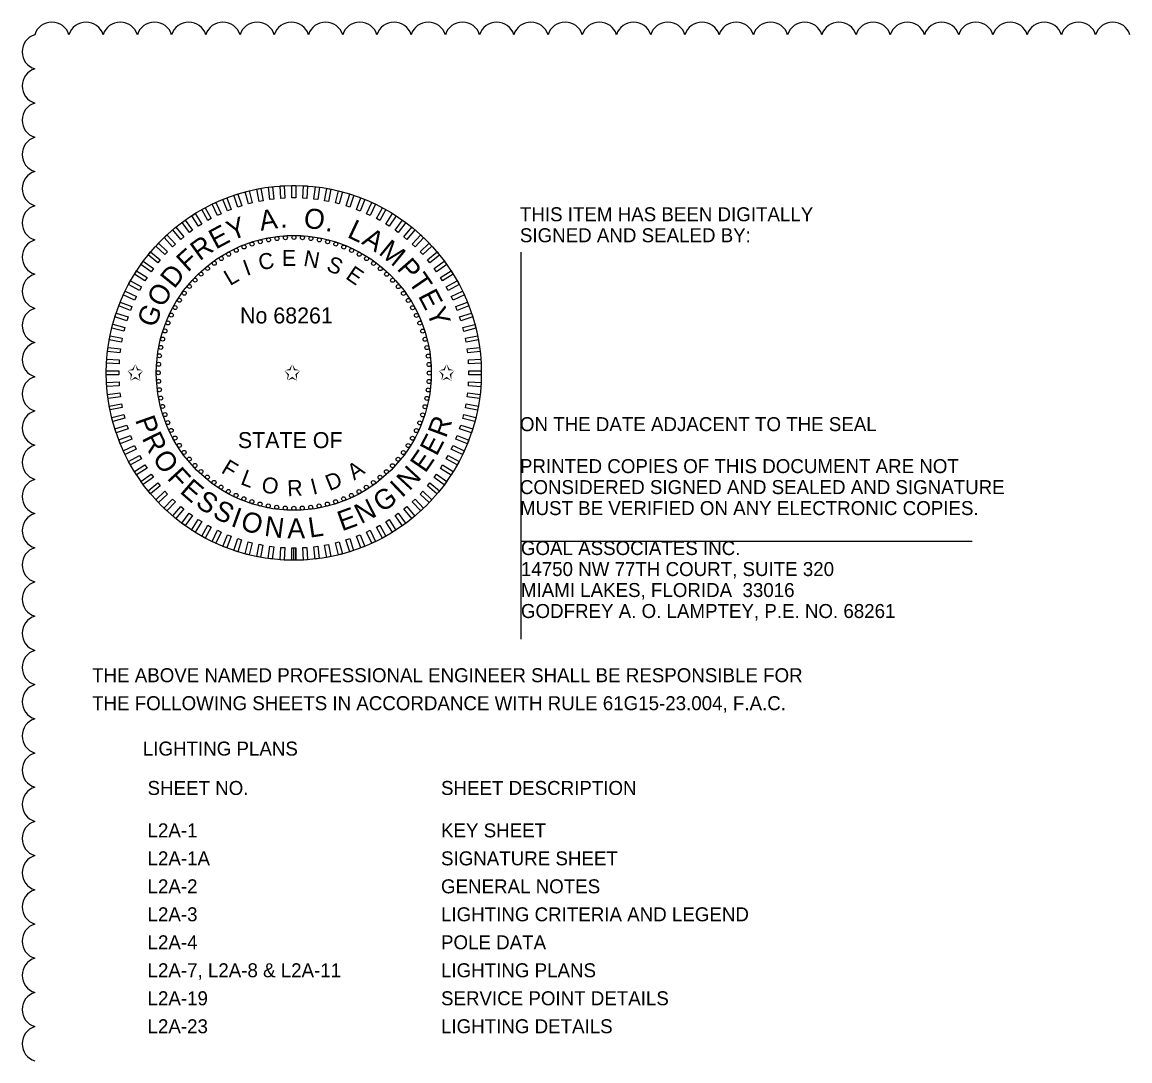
# Model space of a CAD drawing. Extents: x -811 to -790, y -2284 to -2178.
# Drawn here: x -810.85 to -805.31, y -2194.13 to -2188.94 of the extents above; entities that cross this region are included whole.
import ezdxf

# ---------------------------------------------------------------- set-up
doc = ezdxf.new("R2010")
doc.units = 0
for name, color, linetype in [('AdhocPoint_dp', 7, 'Continuous'), ('PlotBorder_dp', 7, 'Continuous'), ('TextMinor', 7, 'Continuous'), ('TextMisc', 7, 'Continuous'), ('TextShtNo', 7, 'Continuous'), ('TextTitle', 7, 'Continuous')]:
    doc.layers.add(name, color=color, linetype=linetype)

msp = doc.modelspace()

# ---------------------------------------------------------------- linework, layer by layer
at = {"layer": 'AdhocPoint_dp'}
for p, q in [((-808.3546, -2190.0892), (-808.3546, -2192.0239)), ((-808.3546, -2191.5339), (-806.0979, -2191.5339))]:
    msp.add_line(p, q, dxfattribs=at)
at = {"layer": 'TextMinor'}
for radius in [0.9375, 0.6875]:
    msp.add_circle((-809.4901, -2190.6926), radius, dxfattribs=at)
at = {"layer": 'TextShtNo'}
for p, q in [((-809.5001, -2191.6301), (-809.5003, -2191.5676)), ((-809.4901, -2191.6301), (-809.4903, -2191.5676)), ((-809.4801, -2191.6301), (-809.4803, -2191.5676))]:
    msp.add_line(p, q, dxfattribs=at)
for points in [[(-809.5897, -2189.8232), (-809.6097, -2189.8257), (-809.6175, -2189.7638), (-809.5975, -2189.7612)], [(-809.5349, -2189.8187), (-809.555, -2189.8199), (-809.559, -2189.7576), (-809.5388, -2189.7563)], [(-809.4799, -2189.8176), (-809.5001, -2189.8176), (-809.5001, -2189.7551), (-809.4799, -2189.7551)], [(-809.425, -2189.8199), (-809.4452, -2189.8187), (-809.4412, -2189.7563), (-809.4211, -2189.7576)], [(-809.3703, -2189.8257), (-809.3904, -2189.8232), (-809.3825, -2189.7613), (-809.3625, -2189.7638)], [(-809.8028, -2189.8753), (-809.8215, -2189.8827), (-809.8445, -2189.8246), (-809.8258, -2189.8172)], [(-809.7508, -2189.8572), (-809.77, -2189.8635), (-809.7893, -2189.8041), (-809.7701, -2189.7979)], [(-809.6979, -2189.8425), (-809.7174, -2189.8475), (-809.7329, -2189.7871), (-809.7134, -2189.782)], [(-809.6441, -2189.8312), (-809.6639, -2189.8349), (-809.6756, -2189.7736), (-809.6558, -2189.7698)], [(-809.3162, -2189.835), (-809.336, -2189.8312), (-809.3243, -2189.7699), (-809.3045, -2189.7736)], [(-809.2626, -2189.8476), (-809.2822, -2189.8426), (-809.2667, -2189.7821), (-809.2471, -2189.7871)], [(-809.21, -2189.8635), (-809.2292, -2189.8573), (-809.2099, -2189.7979), (-809.1907, -2189.8042)], [(-809.1585, -2189.8828), (-809.1773, -2189.8753), (-809.1543, -2189.8173), (-809.1355, -2189.8247)], [(-809.9027, -2189.9209), (-809.9204, -2189.9306), (-809.9505, -2189.8759), (-809.9328, -2189.8662)], [(-809.8535, -2189.8965), (-809.8717, -2189.9051), (-809.8983, -2189.8486), (-809.8801, -2189.84)], [(-809.1083, -2189.9052), (-809.1266, -2189.8966), (-809.1, -2189.8401), (-809.0817, -2189.8487)], [(-809.0596, -2189.9307), (-809.0773, -2189.921), (-809.0473, -2189.8663), (-809.0296, -2189.876)], [(-809.9962, -2189.9787), (-810.0125, -2189.9906), (-810.0492, -2189.94), (-810.0329, -2189.9282)], [(-809.9504, -2189.9483), (-809.9674, -2189.9591), (-810.0009, -2189.9064), (-809.9838, -2189.8956)], [(-809.0127, -2189.9592), (-809.0297, -2189.9484), (-808.9962, -2189.8957), (-808.9792, -2189.9065)], [(-808.9676, -2189.9907), (-808.9839, -2189.9788), (-808.9472, -2189.9283), (-808.9308, -2189.9402)], [(-810.04, -2190.0119), (-810.0556, -2190.0247), (-810.0954, -2189.9766), (-810.0798, -2189.9638)], [(-808.9245, -2190.0249), (-808.9401, -2190.012), (-808.9003, -2189.9639), (-808.8847, -2189.9768)], [(-810.0817, -2190.0478), (-810.0964, -2190.0616), (-810.1392, -2190.0161), (-810.1244, -2190.0022)], [(-808.8837, -2190.0617), (-808.8984, -2190.0479), (-808.8557, -2190.0024), (-808.841, -2190.0162)], [(-810.1579, -2190.127), (-810.1707, -2190.1425), (-810.2188, -2190.1027), (-810.206, -2190.0872)], [(-810.121, -2190.0862), (-810.1348, -2190.1009), (-810.1804, -2190.0581), (-810.1665, -2190.0434)], [(-808.8453, -2190.101), (-808.8591, -2190.0863), (-808.8136, -2190.0436), (-808.7998, -2190.0583)], [(-808.8094, -2190.1427), (-808.8223, -2190.1271), (-808.7742, -2190.0873), (-808.7613, -2190.1029)], [(-810.192, -2190.17), (-810.2039, -2190.1864), (-810.2544, -2190.1497), (-810.2426, -2190.1333)], [(-808.7762, -2190.1865), (-808.7881, -2190.1702), (-808.7376, -2190.1335), (-808.7257, -2190.1498)], [(-810.2235, -2190.2151), (-810.2343, -2190.2322), (-810.287, -2190.1987), (-810.2762, -2190.1817)], [(-808.7459, -2190.2323), (-808.7567, -2190.2153), (-808.7039, -2190.1818), (-808.6931, -2190.1989)], [(-810.252, -2190.2621), (-810.2617, -2190.2798), (-810.3164, -2190.2497), (-810.3067, -2190.232)], [(-808.7184, -2190.28), (-808.7281, -2190.2623), (-808.6734, -2190.2322), (-808.6637, -2190.2499)], [(-810.2775, -2190.3108), (-810.2861, -2190.3291), (-810.3426, -2190.3025), (-810.334, -2190.2842)], [(-808.694, -2190.3292), (-808.7026, -2190.311), (-808.6461, -2190.2844), (-808.6375, -2190.3027)], [(-810.3, -2190.361), (-810.3074, -2190.3798), (-810.3654, -2190.3568), (-810.358, -2190.338)], [(-808.6728, -2190.3799), (-808.6802, -2190.3612), (-808.6222, -2190.3382), (-808.6147, -2190.357)], [(-810.3192, -2190.4125), (-810.3254, -2190.4317), (-810.3848, -2190.4124), (-810.3786, -2190.3932)], [(-808.6548, -2190.4319), (-808.661, -2190.4127), (-808.6016, -2190.3934), (-808.5954, -2190.4126)], [(-810.3351, -2190.4651), (-810.3401, -2190.4847), (-810.4006, -2190.4691), (-810.3956, -2190.4496)], [(-808.64, -2190.4849), (-808.6451, -2190.4653), (-808.5846, -2190.4498), (-808.5796, -2190.4693)], [(-810.3477, -2190.5186), (-810.3515, -2190.5385), (-810.4129, -2190.5268), (-810.4091, -2190.5069)], [(-808.6287, -2190.5386), (-808.6325, -2190.5188), (-808.5711, -2190.5071), (-808.5673, -2190.5269)], [(-810.357, -2190.5728), (-810.3595, -2190.5928), (-810.4215, -2190.585), (-810.4189, -2190.565)], [(-808.6207, -2190.593), (-808.6232, -2190.573), (-808.5613, -2190.5652), (-808.5588, -2190.5852)], [(-810.3628, -2190.6275), (-810.3641, -2190.6476), (-810.4264, -2190.6437), (-810.4251, -2190.6236)], [(-808.6162, -2190.6478), (-808.6174, -2190.6277), (-808.5551, -2190.6238), (-808.5539, -2190.6439)], [(-810.3652, -2190.6824), (-810.3652, -2190.7026), (-810.4276, -2190.7026), (-810.4276, -2190.6824)], [(-808.6151, -2190.7028), (-808.6151, -2190.6826), (-808.5527, -2190.6826), (-808.5527, -2190.7028)], [(-810.3641, -2190.7374), (-810.3628, -2190.7575), (-810.4251, -2190.7614), (-810.4264, -2190.7413)], [(-808.6175, -2190.7577), (-808.6162, -2190.7376), (-808.5539, -2190.7415), (-808.5551, -2190.7616)], [(-810.3595, -2190.7922), (-810.357, -2190.8122), (-810.4189, -2190.82), (-810.4215, -2190.8)], [(-808.6233, -2190.8124), (-808.6207, -2190.7923), (-808.5588, -2190.8002), (-808.5613, -2190.8202)], [(-810.3516, -2190.8466), (-810.3478, -2190.8664), (-810.4091, -2190.8781), (-810.4129, -2190.8583)], [(-808.6325, -2190.8666), (-808.6287, -2190.8467), (-808.5674, -2190.8584), (-808.5712, -2190.8783)], [(-810.3402, -2190.9003), (-810.3352, -2190.9199), (-810.3957, -2190.9354), (-810.4007, -2190.9159)], [(-808.6451, -2190.9201), (-808.6401, -2190.9005), (-808.5796, -2190.916), (-808.5846, -2190.9356)], [(-810.3255, -2190.9533), (-810.3192, -2190.9725), (-810.3786, -2190.9918), (-810.3849, -2190.9726)], [(-808.6611, -2190.9727), (-808.6548, -2190.9535), (-808.5954, -2190.9728), (-808.6017, -2190.992)], [(-810.3075, -2191.0052), (-810.3, -2191.024), (-810.3581, -2191.047), (-810.3655, -2191.0282)], [(-808.6803, -2191.0242), (-808.6729, -2191.0054), (-808.6148, -2191.0284), (-808.6222, -2191.0472)], [(-810.2862, -2191.0559), (-810.2776, -2191.0742), (-810.3341, -2191.1008), (-810.3427, -2191.0825)], [(-808.7027, -2191.0744), (-808.6941, -2191.0561), (-808.6376, -2191.0827), (-808.6462, -2191.101)], [(-810.2618, -2191.1052), (-810.2521, -2191.1229), (-810.3068, -2191.153), (-810.3165, -2191.1353)], [(-808.7282, -2191.1231), (-808.7185, -2191.1054), (-808.6638, -2191.1355), (-808.6735, -2191.1532)], [(-810.2344, -2191.1529), (-810.2236, -2191.1699), (-810.2763, -2191.2034), (-810.2871, -2191.1863)], [(-810.204, -2191.1987), (-810.1922, -2191.215), (-810.2427, -2191.2517), (-810.2545, -2191.2354)], [(-808.7882, -2191.2152), (-808.7763, -2191.1988), (-808.7258, -2191.2355), (-808.7377, -2191.2519)], [(-808.7568, -2191.1701), (-808.746, -2191.153), (-808.6932, -2191.1865), (-808.704, -2191.2035)], [(-810.1708, -2191.2425), (-810.158, -2191.2581), (-810.2061, -2191.2979), (-810.2189, -2191.2823)], [(-808.8224, -2191.2582), (-808.8095, -2191.2427), (-808.7614, -2191.2825), (-808.7743, -2191.298)], [(-810.135, -2191.2842), (-810.1211, -2191.2989), (-810.1667, -2191.3416), (-810.1805, -2191.3269)], [(-808.8592, -2191.299), (-808.8454, -2191.2843), (-808.7999, -2191.327), (-808.8137, -2191.3418)], [(-810.0965, -2191.3235), (-810.0818, -2191.3373), (-810.1246, -2191.3828), (-810.1393, -2191.369)], [(-810.0557, -2191.3603), (-810.0402, -2191.3732), (-810.08, -2191.4213), (-810.0955, -2191.4084)], [(-808.9402, -2191.3733), (-808.9247, -2191.3604), (-808.8848, -2191.4086), (-808.9004, -2191.4214)], [(-808.8985, -2191.3374), (-808.8838, -2191.3236), (-808.8411, -2191.3691), (-808.8558, -2191.383)], [(-810.0127, -2191.3945), (-809.9964, -2191.4064), (-810.0331, -2191.4569), (-810.0494, -2191.445)], [(-808.984, -2191.4065), (-808.9677, -2191.3946), (-808.931, -2191.4451), (-808.9473, -2191.457)], [(-809.9676, -2191.426), (-809.9505, -2191.4368), (-809.984, -2191.4895), (-810.001, -2191.4787)], [(-809.9206, -2191.4545), (-809.9029, -2191.4642), (-809.933, -2191.5189), (-809.9507, -2191.5092)], [(-809.0775, -2191.4643), (-809.0598, -2191.4546), (-809.0297, -2191.5093), (-809.0474, -2191.519)], [(-809.0299, -2191.4369), (-809.0128, -2191.4261), (-808.9794, -2191.4788), (-808.9964, -2191.4896)], [(-809.8719, -2191.48), (-809.8536, -2191.4886), (-809.8802, -2191.5451), (-809.8985, -2191.5365)], [(-809.8217, -2191.5024), (-809.8029, -2191.5099), (-809.8259, -2191.5679), (-809.8447, -2191.5605)], [(-809.7702, -2191.5217), (-809.751, -2191.5279), (-809.7703, -2191.5873), (-809.7895, -2191.581)], [(-809.2294, -2191.5279), (-809.2102, -2191.5217), (-809.1909, -2191.5811), (-809.2101, -2191.5873)], [(-809.1775, -2191.5099), (-809.1587, -2191.5025), (-809.1357, -2191.5606), (-809.1545, -2191.568)], [(-809.1268, -2191.4887), (-809.1085, -2191.4801), (-809.0819, -2191.5366), (-809.1002, -2191.5452)], [(-809.7176, -2191.5376), (-809.698, -2191.5426), (-809.7136, -2191.6031), (-809.7331, -2191.5981)], [(-809.6641, -2191.5502), (-809.6443, -2191.554), (-809.656, -2191.6153), (-809.6758, -2191.6116)], [(-809.6099, -2191.5594), (-809.5899, -2191.562), (-809.5977, -2191.6239), (-809.6177, -2191.6214)], [(-809.5552, -2191.5653), (-809.5351, -2191.5665), (-809.539, -2191.6288), (-809.5592, -2191.6276)], [(-809.5003, -2191.5676), (-809.4801, -2191.5676), (-809.4801, -2191.6301), (-809.5003, -2191.6301)], [(-809.4453, -2191.5665), (-809.4252, -2191.5653), (-809.4213, -2191.6276), (-809.4414, -2191.6289)], [(-809.3906, -2191.562), (-809.3705, -2191.5595), (-809.3627, -2191.6214), (-809.3827, -2191.624)], [(-809.3362, -2191.554), (-809.3163, -2191.5503), (-809.3046, -2191.6116), (-809.3245, -2191.6154)], [(-809.2824, -2191.5427), (-809.2628, -2191.5376), (-809.2473, -2191.5981), (-809.2668, -2191.6031)]]:
    msp.add_lwpolyline(points, close=True, dxfattribs=at)
for centre in [(-809.6989, -2190.0481), (-809.6581, -2190.0363), (-809.6165, -2190.027), (-809.5745, -2190.0204), (-809.5321, -2190.0164), (-809.4896, -2190.0151), (-809.447, -2190.0165), (-809.4047, -2190.0205), (-809.3626, -2190.0272), (-809.3211, -2190.0366), (-809.2802, -2190.0485), (-809.816, -2190.0987), (-809.7781, -2190.0794), (-809.739, -2190.0625), (-809.2402, -2190.0629), (-809.2012, -2190.0798), (-809.1633, -2190.0992), (-809.8879, -2190.1442), (-809.8527, -2190.1203), (-809.1266, -2190.1209), (-809.0915, -2190.1448), (-809.9535, -2190.1984), (-809.9215, -2190.1702), (-809.0579, -2190.171), (-809.026, -2190.1991), (-810.0118, -2190.2603), (-809.9836, -2190.2284), (-808.9959, -2190.2292), (-808.9678, -2190.2612), (-810.0379, -2190.2939), (-808.9417, -2190.2948), (-810.0835, -2190.3657), (-810.0618, -2190.3291), (-808.9178, -2190.3301), (-808.8962, -2190.3667), (-810.1029, -2190.4036), (-808.8769, -2190.4047), (-810.1343, -2190.4827), (-810.1198, -2190.4427), (-808.86, -2190.4437), (-808.8456, -2190.4838), (-810.1462, -2190.5236), (-808.8338, -2190.5247), (-810.1555, -2190.5651), (-808.8245, -2190.5662), (-810.1662, -2190.6495), (-810.1622, -2190.6071), (-808.8179, -2190.6082), (-808.814, -2190.6506), (-810.1676, -2190.692), (-808.8127, -2190.6932), (-810.1663, -2190.7346), (-808.814, -2190.7357), (-810.1623, -2190.7769), (-810.1557, -2190.819), (-808.8248, -2190.8201), (-808.8181, -2190.7781), (-810.1464, -2190.8605), (-808.8341, -2190.8616), (-810.1346, -2190.9014), (-808.846, -2190.9025), (-810.1202, -2190.9415), (-810.1034, -2190.9805), (-808.8774, -2190.9816), (-808.8604, -2190.9425), (-810.0841, -2191.0185), (-808.8967, -2191.0195), (-810.0624, -2191.0551), (-810.0385, -2191.0903), (-808.9424, -2191.0913), (-808.9184, -2191.0561), (-810.0125, -2191.124), (-809.9844, -2191.1559), (-808.9967, -2191.1568), (-808.9685, -2191.1249), (-809.9543, -2191.1861), (-809.0268, -2191.1868), (-809.9224, -2191.2142), (-809.8888, -2191.2403), (-809.8536, -2191.2643), (-809.1276, -2191.2649), (-809.0924, -2191.241), (-809.0587, -2191.215), (-809.817, -2191.286), (-809.7791, -2191.3053), (-809.74, -2191.3223), (-809.2413, -2191.3227), (-809.2022, -2191.3058), (-809.1642, -2191.2865), (-809.7, -2191.3367), (-809.6591, -2191.3486), (-809.6176, -2191.358), (-809.5756, -2191.3647), (-809.5332, -2191.3687), (-809.4901, -2191.3701), (-809.4481, -2191.3688), (-809.4058, -2191.3648), (-809.3637, -2191.3582), (-809.3222, -2191.3489), (-809.2813, -2191.3371)]:
    msp.add_circle(centre, 0.01, dxfattribs=at)
at = {"layer": 'TextTitle'}
for centre, start, end in [((-810.7002, -2189.0276), 17.5, 162.5), ((-810.5291, -2189.0276), 17.5, 162.5), ((-810.358, -2189.0276), 17.5, 162.5), ((-810.1868, -2189.0276), 17.5, 162.5), ((-810.0157, -2189.0276), 17.5, 162.5), ((-809.8446, -2189.0276), 17.5, 162.5), ((-809.6735, -2189.0276), 17.5, 162.5), ((-809.5024, -2189.0276), 17.5, 162.5), ((-809.3312, -2189.0276), 17.5, 162.5), ((-809.1601, -2189.0276), 17.5, 162.5), ((-808.989, -2189.0276), 17.5, 162.5), ((-808.8179, -2189.0276), 17.5, 162.5), ((-808.6467, -2189.0276), 17.5, 162.5), ((-808.4756, -2189.0276), 17.5, 162.5), ((-808.3045, -2189.0276), 17.5, 162.5), ((-808.1334, -2189.0276), 17.5, 162.5), ((-807.9622, -2189.0276), 17.5, 162.5), ((-807.7911, -2189.0276), 17.5, 162.5), ((-807.62, -2189.0276), 17.5, 162.5), ((-807.4489, -2189.0276), 17.5, 162.5), ((-807.2778, -2189.0276), 17.5, 162.5), ((-807.1066, -2189.0276), 17.5, 162.5), ((-806.9355, -2189.0276), 17.5, 162.5), ((-806.7644, -2189.0276), 17.5, 162.5), ((-806.5933, -2189.0276), 17.5, 162.5), ((-806.4221, -2189.0276), 17.5, 162.5), ((-806.251, -2189.0276), 17.5, 162.5), ((-806.0799, -2189.0276), 17.5, 162.5), ((-805.9088, -2189.0276), 17.5, 162.5), ((-805.7377, -2189.0276), 17.5, 162.5), ((-805.5665, -2189.0276), 17.5, 162.5), ((-805.3954, -2189.0276), 17.5, 162.5), ((-810.7588, -2189.0862), 107.5, 252.5), ((-810.7588, -2189.2573), 107.5, 252.5), ((-810.7588, -2189.4284), 107.5, 252.5), ((-810.7588, -2189.5996), 107.5, 252.5), ((-810.7588, -2189.7707), 107.5, 252.5), ((-810.7588, -2189.9418), 107.5, 252.5), ((-810.7588, -2190.1129), 107.5, 252.5), ((-810.7588, -2190.2841), 107.5, 252.5), ((-810.7588, -2190.4552), 107.5, 252.5), ((-810.7588, -2190.6263), 107.5, 252.5), ((-810.7588, -2190.7974), 107.5, 252.5), ((-810.7588, -2190.9685), 107.5, 252.5), ((-810.7588, -2191.1397), 107.5, 252.5), ((-810.7588, -2191.3108), 107.5, 252.5), ((-810.7588, -2191.4819), 107.5, 252.5), ((-810.7588, -2191.653), 107.5, 252.5), ((-810.7588, -2191.8242), 107.5, 252.5), ((-810.7588, -2191.9953), 107.5, 252.5), ((-810.7588, -2192.1664), 107.5, 252.5), ((-810.7588, -2192.3375), 107.5, 252.5), ((-810.7588, -2192.5087), 107.5, 252.5), ((-810.7588, -2192.6798), 107.5, 252.5), ((-810.7588, -2192.8509), 107.5, 252.5), ((-810.7588, -2193.022), 107.5, 252.5), ((-810.7588, -2193.1931), 107.5, 252.5), ((-810.7588, -2193.3643), 107.5, 252.5), ((-810.7588, -2193.5354), 107.5, 252.5), ((-810.7588, -2193.7065), 107.5, 252.5), ((-810.7588, -2193.8776), 107.5, 252.5), ((-810.7588, -2194.0488), 107.5, 252.5)]:
    msp.add_arc(centre, 0.0897, start, end, dxfattribs=at)

# ---------------------------------------------------------------- texts
at = {"layer": 'PlotBorder_dp'}
for s, p in [('THIS ITEM HAS BEEN DIGITALLY', (-808.3596, -2189.934)), ('SIGNED AND SEALED BY:', (-808.3596, -2190.039)), ('ON THE DATE ADJACENT TO THE SEAL', (-808.3596, -2190.984)), ('PRINTED COPIES OF THIS DOCUMENT ARE NOT ', (-808.3596, -2191.194)), ('CONSIDERED SIGNED AND SEALED AND SIGNATURE ', (-808.3596, -2191.299)), ('MUST BE VERIFIED ON ANY ELECTRONIC COPIES.', (-808.3596, -2191.404)), ('GOAL ASSOCIATES INC.', (-808.3546, -2191.6039)), ('14750 NW 77TH COURT, SUITE 320', (-808.3546, -2191.7089)), ('MIAMI LAKES, FLORIDA  33016', (-808.3546, -2191.8139)), ('GODFREY A. O. LAMPTEY, P.E. NO. 68261', (-808.3546, -2191.9189)), ('THE ABOVE NAMED PROFESSIONAL ENGINEER SHALL BE RESPONSIBLE FOR ', (-810.4987, -2192.24)), ('THE FOLLOWING SHEETS IN ACCORDANCE WITH RULE 61G15-23.004, F.A.C.', (-810.4987, -2192.38)), ('LIGHTING PLANS', (-810.245, -2192.6071))]:
    msp.add_text(s, height=0.07, dxfattribs=at).set_placement(p)
at = {"layer": 'TextMisc'}
for s, p in [('SHEET NO.', (-810.2215, -2192.8041)), ('SHEET DESCRIPTION', (-808.7542, -2192.8041)), ('L2A-1', (-810.2215, -2193.0162)), ('KEY SHEET', (-808.7542, -2193.0162)), ('L2A-1A', (-810.2215, -2193.1562)), ('SIGNATURE SHEET', (-808.7542, -2193.1562)), ('L2A-2', (-810.2215, -2193.2962)), ('GENERAL NOTES', (-808.7542, -2193.2962)), ('L2A-3', (-810.2215, -2193.4362)), ('LIGHTING CRITERIA AND LEGEND', (-808.7542, -2193.4362)), ('L2A-4 ', (-810.2215, -2193.5762)), ('POLE DATA', (-808.7542, -2193.5762)), ('L2A-7, L2A-8 & L2A-11', (-810.2215, -2193.7162)), ('LIGHTING PLANS', (-808.7542, -2193.7162)), ('L2A-19', (-810.2215, -2193.8562)), ('SERVICE POINT DETAILS', (-808.7542, -2193.8562)), ('L2A-23', (-810.2215, -2193.9962)), ('LIGHTING DETAILS', (-808.7542, -2193.9962))]:
    msp.add_text(s, height=0.07, dxfattribs=at).set_placement(p)
at = {"layer": 'TextShtNo'}
for s, height, rotation, p in [('O', 0.1, 352.1877, (-809.4449, -2189.9645)), ('Y', 0.1, 21.0633, (-809.8021, -2190.0332)), ('A', 0.1, 8.8088, (-809.6551, -2189.982)), ('L', 0.1, 334.6727, (-809.2279, -2190.0118)), ('E', 0.1, 28.1055, (-809.8806, -2190.0764)), ('.', 0.1, 1.0418, (-809.5575, -2189.9662)), ('.', 0.1, 343.5268, (-809.3358, -2189.9796)), ('A', 0.1, 328.4096, (-809.1552, -2190.0445)), ('R', 0.1, 35.9269, (-809.9609, -2190.1353)), ('M', 0.1, 320.6426, (-809.0707, -2190.0957)), ('F', 0.1, 42.3772, (-810.0205, -2190.1917)), ('C', 0.08, 12.2025, (-809.6579, -2190.181)), ('E', 0.08, 0.4186, (-809.5498, -2190.1575)), ('N', 0.08, 349.2914, (-809.4455, -2190.1561)), ('I', 0.08, 20.0117, (-809.7258, -2190.2085)), ('S', 0.08, 337.0221, (-809.3325, -2190.1778)), ('P', 0.1, 311.1966, (-808.9784, -2190.1727)), ('D', 0.1, 50.8569, (-810.0886, -2190.2754)), ('L', 0.08, 30.4021, (-809.8093, -2190.259)), ('E', 0.08, 325.8663, (-809.2358, -2190.218)), ('T', 0.1, 304.4563, (-808.9209, -2190.2363)), ('O', 0.1, 59.5178, (-810.1446, -2190.3702)), ('E', 0.1, 297.6315, (-808.8707, -2190.3072)), ('G', 0.1, 68.0518, (-810.1851, -2190.4709)), ('Y', 0.1, 290.5893, (-808.8281, -2190.386)), ('P', 0.1, 289.4055, (-810.2848, -2190.9272)), ('R', 0.1, 69.5134, (-808.7299, -2191.0223)), ('R', 0.1, 296.1458, (-810.2518, -2191.0188)), ('E', 0.1, 62.4712, (-808.7761, -2191.113)), ('O', 0.1, 303.9671, (-810.2003, -2191.1194)), ('E', 0.1, 55.4289, (-808.833, -2191.1974)), ('F', 0.08, 328.7241, (-809.8582, -2191.1892)), ('A', 0.08, 34.4992, (-809.1883, -2191.232)), ('F', 0.1, 312.628, (-810.1279, -2191.2215)), ('L', 0.08, 339.2916, (-809.7609, -2191.2483)), ('D', 0.08, 22.0128, (-809.312, -2191.2845)), ('N', 0.1, 47.1788, (-808.9123, -2191.2864)), ('E', 0.1, 319.0783, (-810.0645, -2191.2898)), ('O', 0.08, 349.6821, (-809.6562, -2191.288)), ('R', 0.08, 2.3398, (-809.5217, -2191.3099)), ('I', 0.08, 14.2037, (-809.3941, -2191.3032)), ('I', 0.1, 43.6456, (-808.9499, -2191.3209)), ('S', 0.1, 326.1206, (-809.9869, -2191.3557)), ('G', 0.1, 35.1115, (-809.0492, -2191.3941)), ('S', 0.1, 333.193, (-809.9015, -2191.4119)), ('I', 0.1, 340.2654, (-809.8098, -2191.457)), ('E', 0.1, 19.8191, (-809.2498, -2191.4856)), ('N', 0.1, 26.8614, (-809.1544, -2191.4501)), ('O', 0.1, 343.7986, (-809.7621, -2191.4753)), ('N', 0.1, 352.4595, (-809.6411, -2191.5073)), ('A', 0.1, 0.7097, (-809.5227, -2191.5206)), ('L', 0.1, 8.4767, (-809.4105, -2191.5174))]:
    msp.add_text(s, height=height, rotation=rotation, dxfattribs=at).set_placement(p)
for s, p in [('No 68261', (-809.7591, -2190.4454)), ('✩', (-810.3251, -2190.7305)), ('✩', (-809.5404, -2190.7305)), ('✩', (-808.7685, -2190.7305)), ('STATE OF', (-809.7698, -2191.0688))]:
    msp.add_text(s, height=0.08, dxfattribs=at).set_placement(p)

doc.saveas('drawing.dxf')
